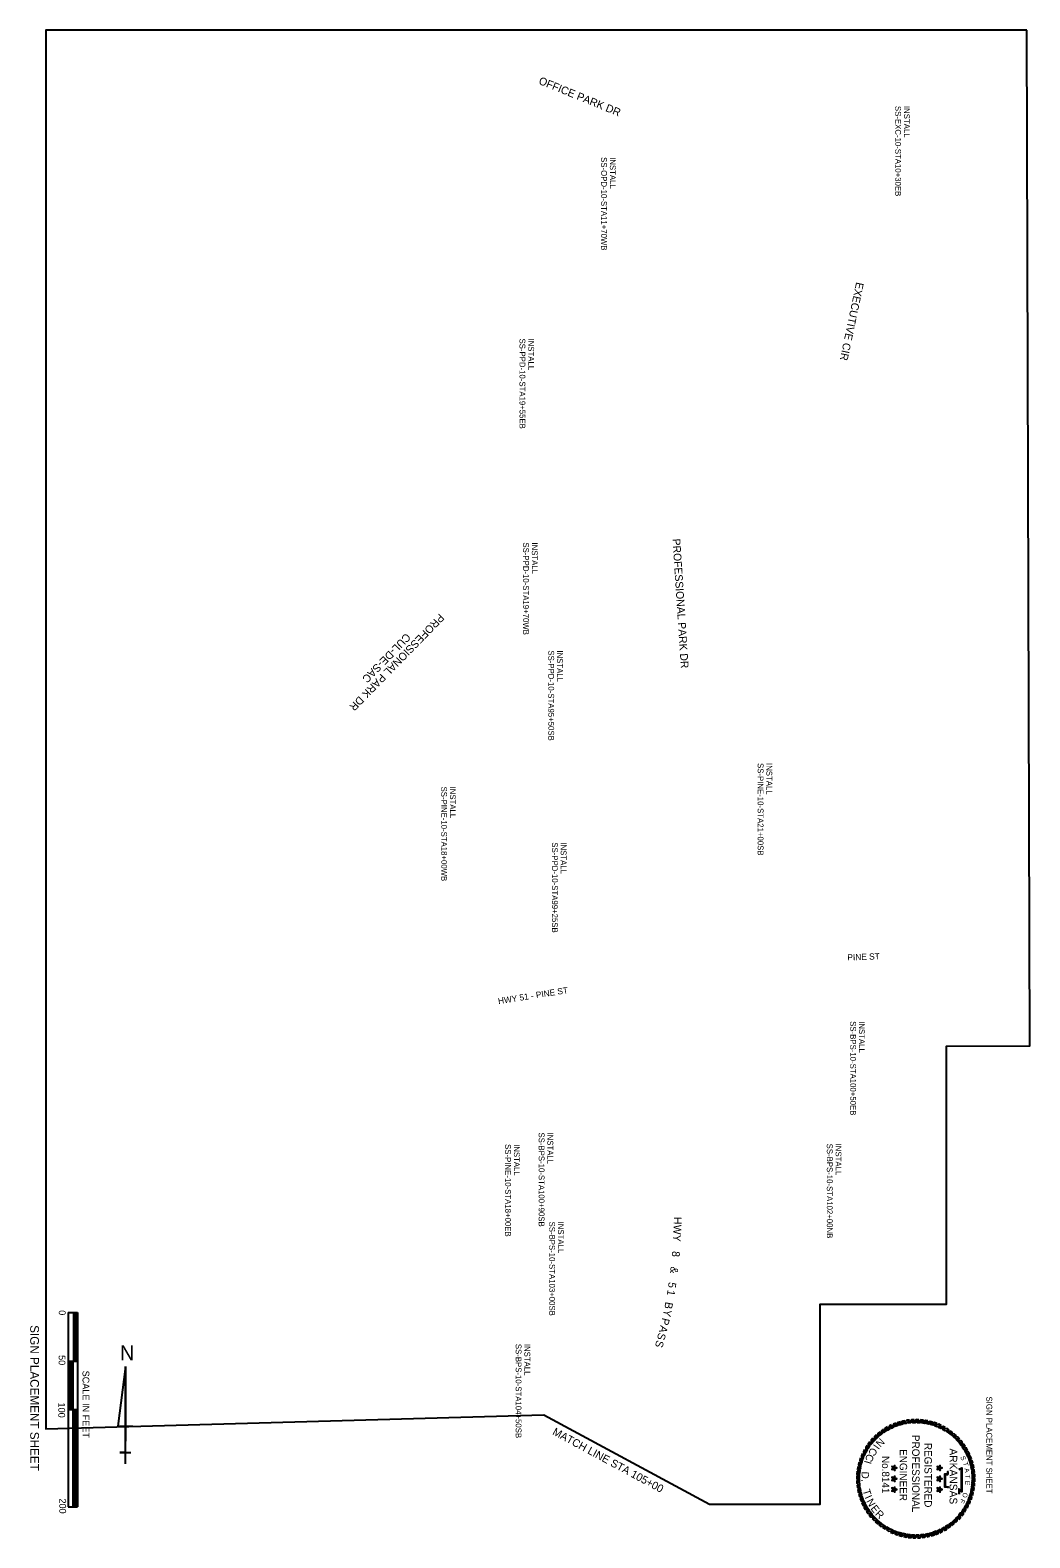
# Model space of a CAD drawing. Extents: x 981987 to 983016, y 1842087 to 1843638.
import ezdxf

# ---------------------------------------------------------------- set-up
doc = ezdxf.new("R2010")
doc.units = 0
for name, color, linetype in [('5', 7, 'Continuous'), ('63', 7, 'Continuous'), ('G-ANNO-SYMB', 7, 'Continuous'), ('G-ANNO-TEXT', 7, 'Continuous'), ('Level 10', 7, 'Continuous'), ('Plan Notes', 7, 'Continuous'), ('R_Annotation', 7, 'Continuous'), ('R_No Plot', 7, 'Continuous')]:
    doc.layers.add(name, color=color, linetype=linetype)

msp = doc.modelspace()

# ---------------------------------------------------------------- linework, layer by layer
at = {"layer": '5'}
msp.add_line((982515.7, 1842213.5), (982686.3, 1842121.4), dxfattribs=at)
at = {"layer": '63'}
for p, q in [((982085, 1842263.2), (982077.3, 1842201.7)), ((982085, 1842163.2), (982085, 1842263.2)), ((982085, 1842263.2), (982085, 1842186.3)), ((982077.3, 1842201.7), (982092.6, 1842201.7)), ((982085, 1842174.7), (982079.2, 1842174.7)), ((982079.2, 1842174.7), (982090.7, 1842174.7)), ((982085, 1842163.2), (982085, 1842186.3)), ((982085, 1842163.2), (982085, 1842174.7))]:
    msp.add_line(p, q, dxfattribs=at)
at = {"layer": 'G-ANNO-SYMB'}
for points in [[(982882.6, 1842206.4), (982880.1, 1842205.6), (982877.5, 1842201.8), (982880.1, 1842202.7)], [(982887.3, 1842207.4), (982884.7, 1842206.9), (982881.8, 1842203.2), (982884.5, 1842204)], [(982892, 1842208.1), (982889.4, 1842207.8), (982886.2, 1842204.4), (982889, 1842204.9)], [(982896.7, 1842208.4), (982894.1, 1842208.3), (982890.7, 1842205.2), (982893.5, 1842205.5)], [(982901.5, 1842208.4), (982898.9, 1842208.5), (982895.2, 1842205.6), (982898.1, 1842205.7)], [(982906.3, 1842208), (982903.7, 1842208.2), (982899.8, 1842205.7), (982902.6, 1842205.5)], [(982911, 1842207.2), (982908.4, 1842207.7), (982904.3, 1842205.4), (982907.1, 1842205)], [(982915.6, 1842206), (982913.1, 1842206.7), (982908.8, 1842204.8), (982911.6, 1842204.2)], [(982920.1, 1842204.5), (982917.7, 1842205.4), (982913.3, 1842203.8), (982916, 1842203)], [(982857.7, 1842192.8), (982855.8, 1842191), (982855.2, 1842186.3), (982857.2, 1842188.4)], [(982861.4, 1842195.8), (982859.3, 1842194.2), (982858.4, 1842189.6), (982860.5, 1842191.5)], [(982865.2, 1842198.6), (982863.1, 1842197.1), (982861.8, 1842192.6), (982864, 1842194.4)], [(982869.3, 1842201), (982867.1, 1842199.7), (982865.4, 1842195.4), (982867.8, 1842196.9)], [(982873.6, 1842203.2), (982871.3, 1842202), (982869.3, 1842197.8), (982871.8, 1842199.2)], [(982878, 1842204.9), (982875.6, 1842204), (982873.3, 1842199.9), (982875.9, 1842201.1)], [(982924.5, 1842202.6), (982922.1, 1842203.7), (982917.6, 1842202.4), (982920.3, 1842201.4)], [(982928.7, 1842200.4), (982926.5, 1842201.6), (982921.9, 1842200.8), (982924.4, 1842199.6)], [(982932.8, 1842197.9), (982930.6, 1842199.3), (982926, 1842198.8), (982928.4, 1842197.4)], [(982936.6, 1842195), (982934.6, 1842196.6), (982929.9, 1842196.4), (982932.2, 1842194.9)], [(982940.2, 1842191.9), (982938.3, 1842193.6), (982933.6, 1842193.8), (982935.8, 1842192.1)], [(982943.6, 1842188.5), (982941.8, 1842190.4), (982937.1, 1842190.9), (982939.2, 1842189)], [(982845.8, 1842177.9), (982844.5, 1842175.7), (982845.4, 1842171.1), (982846.6, 1842173.6)], [(982848.3, 1842182), (982846.9, 1842179.8), (982847.4, 1842175.2), (982848.8, 1842177.6)], [(982851.1, 1842185.8), (982849.5, 1842183.7), (982849.7, 1842179.1), (982851.3, 1842181.4)], [(982854.3, 1842189.4), (982852.5, 1842187.5), (982852.3, 1842182.8), (982854.1, 1842185)], [(982946.6, 1842184.8), (982945, 1842186.8), (982940.4, 1842187.8), (982942.3, 1842185.7)], [(982949.4, 1842180.9), (982947.9, 1842183.1), (982943.4, 1842184.4), (982945.2, 1842182.1)], [(982951.8, 1842176.8), (982950.5, 1842179.1), (982946.2, 1842180.7), (982947.7, 1842178.4)], [(982954, 1842172.5), (982952.8, 1842174.9), (982948.6, 1842176.9), (982950, 1842174.4)], [(982839, 1842160.2), (982838.5, 1842157.6), (982840.8, 1842153.5), (982841.1, 1842156.3)], [(982840.1, 1842164.8), (982839.5, 1842162.3), (982841.4, 1842158), (982842, 1842160.8)], [(982841.7, 1842169.3), (982840.8, 1842166.9), (982842.4, 1842162.5), (982843.2, 1842165.2)], [(982843.5, 1842173.7), (982842.5, 1842171.3), (982843.7, 1842166.8), (982844.7, 1842169.5)], [(982876.1, 1842158.8), (982875.8, 1842159.8), (982873.9, 1842160.4), (982875.1, 1842158.8)], [(982876.1, 1842158.8), (982875.1, 1842158.8), (982873.9, 1842157.2), (982875.8, 1842157.8)], [(982876.1, 1842158.8), (982877, 1842159.4), (982877, 1842161.4), (982875.8, 1842159.8)], [(982876.1, 1842158.8), (982875.8, 1842157.8), (982877, 1842156.1), (982877, 1842158.2)], [(982876.1, 1842158.8), (982877, 1842158.2), (982878.9, 1842158.8), (982877, 1842159.4)], [(982922.7, 1842158.8), (982922.4, 1842159.8), (982920.4, 1842160.4), (982921.6, 1842158.8)], [(982922.7, 1842158.8), (982921.6, 1842158.8), (982920.4, 1842157.2), (982922.4, 1842157.8)], [(982922.7, 1842158.8), (982923.5, 1842159.4), (982923.5, 1842161.4), (982922.4, 1842159.8)], [(982922.7, 1842158.8), (982922.4, 1842157.8), (982923.5, 1842156.1), (982923.5, 1842158.2)], [(982922.7, 1842158.8), (982923.5, 1842158.2), (982925.5, 1842158.8), (982923.5, 1842159.4)], [(982955.7, 1842168.1), (982954.8, 1842170.5), (982950.7, 1842172.8), (982951.9, 1842170.3)], [(982957.2, 1842163.6), (982956.4, 1842166.1), (982952.6, 1842168.7), (982953.5, 1842166)], [(982958.2, 1842158.9), (982957.7, 1842161.5), (982954, 1842164.4), (982954.8, 1842161.6)], [(982958.9, 1842154.2), (982958.6, 1842156.8), (982955.2, 1842159.9), (982955.7, 1842157.2)], [(982837.8, 1842150.7), (982837.7, 1842148.1), (982840.6, 1842144.4), (982840.5, 1842147.2)], [(982837.7, 1842145.9), (982837.8, 1842143.3), (982841, 1842139.9), (982840.7, 1842142.7)], [(982838.2, 1842155.5), (982837.9, 1842152.9), (982840.5, 1842149), (982840.6, 1842151.8)], [(982876.1, 1842147.7), (982875.8, 1842148.7), (982873.9, 1842149.3), (982875.1, 1842147.7)], [(982876.1, 1842147.7), (982875.1, 1842147.7), (982873.9, 1842146), (982875.8, 1842146.7)], [(982876.1, 1842147.7), (982877, 1842148.3), (982877, 1842150.3), (982875.8, 1842148.7)], [(982876.1, 1842147.7), (982875.8, 1842146.7), (982877, 1842145), (982877, 1842147.1)], [(982876.1, 1842147.7), (982877, 1842147.1), (982878.9, 1842147.7), (982877, 1842148.3)], [(982922.7, 1842147.7), (982922.4, 1842148.7), (982920.4, 1842149.3), (982921.6, 1842147.7)], [(982922.7, 1842147.7), (982921.6, 1842147.7), (982920.4, 1842146), (982922.4, 1842146.7)], [(982922.7, 1842147.7), (982923.5, 1842148.3), (982923.5, 1842150.3), (982922.4, 1842148.7)], [(982922.7, 1842147.7), (982922.4, 1842146.7), (982923.5, 1842145), (982923.5, 1842147.1)], [(982922.7, 1842147.7), (982923.5, 1842147.1), (982925.5, 1842147.7), (982923.5, 1842148.3)], [(982959.2, 1842149.4), (982959.1, 1842152), (982956, 1842155.5), (982956.3, 1842152.7)], [(982958.8, 1842139.9), (982959, 1842142.5), (982956.5, 1842146.4), (982956.3, 1842143.5)], [(982959.2, 1842144.6), (982959.3, 1842147.3), (982956.4, 1842150.9), (982956.5, 1842148.1)], [(982838, 1842141.2), (982838.4, 1842138.6), (982841.8, 1842135.4), (982841.2, 1842138.2)], [(982838.7, 1842136.5), (982839.3, 1842133.9), (982842.9, 1842131), (982842.2, 1842133.7)], [(982839.8, 1842131.8), (982840.5, 1842129.3), (982844.4, 1842126.7), (982843.4, 1842129.3)], [(982876.1, 1842136.6), (982875.8, 1842137.6), (982873.9, 1842138.2), (982875.1, 1842136.6)], [(982876.1, 1842136.6), (982875.1, 1842136.6), (982873.9, 1842134.9), (982875.8, 1842135.6)], [(982876.1, 1842136.6), (982877, 1842137.2), (982877, 1842139.2), (982875.8, 1842137.6)], [(982876.1, 1842136.6), (982875.8, 1842135.6), (982877, 1842133.9), (982877, 1842135.9)], [(982876.1, 1842136.6), (982877, 1842135.9), (982878.9, 1842136.6), (982877, 1842137.2)], [(982922.7, 1842136.6), (982922.4, 1842137.6), (982920.4, 1842138.2), (982921.6, 1842136.6)], [(982922.7, 1842136.6), (982921.6, 1842136.6), (982920.4, 1842134.9), (982922.4, 1842135.6)], [(982922.7, 1842136.6), (982923.5, 1842137.2), (982923.5, 1842139.2), (982922.4, 1842137.6)], [(982922.7, 1842136.6), (982922.4, 1842135.6), (982923.5, 1842133.9), (982923.5, 1842135.9)], [(982922.7, 1842136.6), (982923.5, 1842135.9), (982925.5, 1842136.6), (982923.5, 1842137.2)], [(982953.4, 1842121.6), (982954.5, 1842124), (982953.2, 1842128.5), (982952.2, 1842125.9)], [(982955.3, 1842126), (982956.2, 1842128.5), (982954.6, 1842132.9), (982953.8, 1842130.2)], [(982956.8, 1842130.6), (982957.5, 1842133.1), (982955.6, 1842137.3), (982955, 1842134.5)], [(982958, 1842135.2), (982958.5, 1842137.7), (982956.2, 1842141.8), (982955.8, 1842139)], [(982841.2, 1842127.2), (982842.2, 1842124.8), (982846.2, 1842122.5), (982845, 1842125.1)], [(982843, 1842122.8), (982844.1, 1842120.5), (982848.3, 1842118.5), (982847, 1842121)], [(982845.1, 1842118.5), (982846.4, 1842116.3), (982850.8, 1842114.6), (982849.2, 1842117)], [(982847.6, 1842114.4), (982849.1, 1842112.3), (982853.5, 1842111), (982851.8, 1842113.2)], [(982942.7, 1842105.9), (982944.4, 1842107.9), (982944.6, 1842112.5), (982942.9, 1842110.3)], [(982945.8, 1842109.5), (982947.4, 1842111.6), (982947.2, 1842116.3), (982945.7, 1842113.9)], [(982948.7, 1842113.4), (982950.1, 1842115.6), (982949.6, 1842120.2), (982948.2, 1842117.7)], [(982951.2, 1842117.4), (982952.5, 1842119.7), (982951.6, 1842124.3), (982950.4, 1842121.7)], [(982850.3, 1842110.6), (982852, 1842108.5), (982856.5, 1842107.6), (982854.6, 1842109.7)], [(982853.4, 1842106.9), (982855.2, 1842105), (982859.8, 1842104.4), (982857.8, 1842106.4)], [(982856.7, 1842103.5), (982858.7, 1842101.7), (982863.3, 1842101.5), (982861.1, 1842103.3)], [(982860.3, 1842100.3), (982862.4, 1842098.7), (982867.1, 1842098.9), (982864.7, 1842100.5)], [(982864.2, 1842097.5), (982866.4, 1842096.1), (982871, 1842096.6), (982868.5, 1842098)], [(982923.3, 1842092.2), (982925.7, 1842093.3), (982927.7, 1842097.5), (982925.2, 1842096.2)], [(982927.6, 1842094.3), (982929.9, 1842095.6), (982931.5, 1842100), (982929.2, 1842098.4)], [(982931.7, 1842096.8), (982933.9, 1842098.2), (982935.2, 1842102.7), (982932.9, 1842101)], [(982935.6, 1842099.5), (982937.6, 1842101.2), (982938.6, 1842105.7), (982936.5, 1842103.8)], [(982939.3, 1842102.6), (982941.2, 1842104.4), (982941.7, 1842109), (982939.8, 1842107)], [(982868.2, 1842095), (982870.5, 1842093.7), (982875.1, 1842094.6), (982872.5, 1842095.8)], [(982872.4, 1842092.7), (982874.8, 1842091.7), (982879.3, 1842092.9), (982876.7, 1842093.9)], [(982876.8, 1842090.9), (982879.3, 1842090), (982883.7, 1842091.6), (982881, 1842092.4)], [(982881.4, 1842089.3), (982883.9, 1842088.7), (982888.1, 1842090.6), (982885.4, 1842091.2)], [(982886, 1842088.2), (982888.6, 1842087.7), (982892.6, 1842090), (982889.8, 1842090.3)], [(982890.7, 1842087.4), (982893.3, 1842087.1), (982897.2, 1842089.7), (982894.4, 1842089.8)], [(982895.4, 1842087), (982898.1, 1842086.9), (982901.7, 1842089.8), (982898.9, 1842089.7)], [(982900.2, 1842086.9), (982902.8, 1842087), (982906.3, 1842090.2), (982903.5, 1842089.9)], [(982905, 1842087.2), (982907.6, 1842087.6), (982910.7, 1842091), (982908, 1842090.4)], [(982909.7, 1842087.9), (982912.3, 1842088.5), (982915.2, 1842092.1), (982912.4, 1842091.4)], [(982914.4, 1842089), (982916.9, 1842089.7), (982919.5, 1842093.6), (982916.8, 1842092.6)], [(982918.9, 1842090.4), (982921.4, 1842091.4), (982923.6, 1842095.4), (982921.1, 1842094.2)]]:
    msp.add_lwpolyline(points, close=True, dxfattribs=at)
for points in [[(982942.6, 1842157.4), (982945.7, 1842158.8), (982945.7, 1842134.3), (982943.1, 1842136.4), (982943.1, 1842134.7), (982943.1, 1842133.3), (982943, 1842131.9)], [(982932.3, 1842138.2), (982932, 1842138.6), (982931.5, 1842138.7), (982930.2, 1842138.9), (982928.5, 1842138.9), (982928.5, 1842152.6), (982930.8, 1842152.6), (982931.3, 1842152.6), (982931.5, 1842153.1), (982931.5, 1842155.1), (982932, 1842155.4)], [(982932.6, 1842138.4), (982932.2, 1842138.9), (982931.5, 1842139.1), (982930.2, 1842139.3), (982928.9, 1842139.3), (982928.9, 1842152.2), (982930.8, 1842152.2), (982931.6, 1842152.2), (982931.9, 1842153.1), (982931.9, 1842154.9), (982932.2, 1842155.1)], [(982942.8, 1842157.1), (982945.3, 1842158.2), (982945.3, 1842135.1), (982942.7, 1842137.2), (982942.7, 1842134.7), (982942.8, 1842133.3), (982942.6, 1842132)]]:
    msp.add_lwpolyline(points, dxfattribs=at)
at = {"layer": 'Level 10'}
for p, q in [((982026, 1842318.8), (982026, 1842118.8)), ((982026, 1842318.8), (982035.6, 1842318.8)), ((982031.6, 1842318.8), (982031.6, 1842268.8)), ((982032.4, 1842318.8), (982032.4, 1842268.8)), ((982033.2, 1842318.8), (982033.2, 1842268.8)), ((982034, 1842318.8), (982034, 1842268.8)), ((982034.8, 1842318.8), (982034.8, 1842268.8)), ((982035.6, 1842318.8), (982035.6, 1842158.8)), ((982035.6, 1842318.8), (982035.6, 1842278.8)), ((982026, 1842278.8), (982026, 1842238.8)), ((982026, 1842268.8), (982035.6, 1842268.8)), ((982026.8, 1842268.8), (982026.8, 1842218.8)), ((982027.6, 1842268.8), (982027.6, 1842218.8)), ((982028.4, 1842268.8), (982028.4, 1842218.8)), ((982029.2, 1842268.8), (982029.2, 1842218.8)), ((982030, 1842268.8), (982030, 1842218.8)), ((982030.8, 1842268.8), (982030.8, 1842218.8)), ((982035.6, 1842238.8), (982035.6, 1842118.8)), ((982026, 1842218.8), (982035.6, 1842218.8)), ((982030.8, 1842218.8), (982030.8, 1842158.8)), ((982030.8, 1842218.8), (982030.8, 1842118.8)), ((982031.6, 1842218.8), (982031.6, 1842118.8)), ((982032.4, 1842218.8), (982032.4, 1842118.8)), ((982033.2, 1842218.8), (982033.2, 1842118.8)), ((982034, 1842218.8), (982034, 1842118.8)), ((982034.8, 1842218.8), (982034.8, 1842118.8)), ((982026, 1842118.8), (982035.6, 1842118.8))]:
    msp.add_line(p, q, dxfattribs=at)
at = {"layer": 'R_No Plot'}
msp.add_lwpolyline([(983012.9, 1843638.2), (982003.2, 1843638.2), (982003.2, 1842199.2), (982515.7, 1842213.5), (982686.3, 1842121.4), (982800.1, 1842121.4), (982800.1, 1842327.4), (982929.9, 1842327.4), (982929.9, 1842592.9), (983015.9, 1842593.2)], close=True, dxfattribs=at)

# ---------------------------------------------------------------- texts
at = {"layer": '63'}
msp.add_text('N', height=15.4, dxfattribs=at).set_placement((982079.3, 1842269.6))
at = {"layer": 'G-ANNO-SYMB'}
for s, height, rotation, p in [('PROFESSIONAL', 7.642, 270, (982894.7, 1842192.8)), ('C', 7.64, 238.6873, (982853, 1842180.5)), ('I', 7.64, 234.2141, (982855.7, 1842183.9)), ('N', 7.64, 225.2676, (982861.8, 1842190.1)), ('ENGINEER', 7.64, 270, (982881.9, 1842178.2)), ('REGISTERED', 7.64, 270, (982907.4, 1842184.6)), ('ARKANSAS', 7.89, 270, (982933.2, 1842178.9)), ('I', 7.64, 254.3437, (982845.8, 1842167)), ('C', 7.64, 246.5155, (982848.9, 1842174)), ('No.8141', 7.61, 270, (982863.7, 1842171.1)), ('S', 4.84, 289.7726, (982944.2, 1842170.2)), ('T', 4.84, 286.9015, (982947, 1842164)), ('.', 7.64, 274.846, (982842.4, 1842147.3)), ('D', 7.64, 266.6451, (982842.9, 1842155.3)), ('A', 4.84, 278.6788, (982948.5, 1842158.2)), ('E', 4.84, 266.672, (982949.3, 1842145.7)), ('T', 4.84, 271.4789, (982949.5, 1842151.9)), ('T', 7.64, 286.7747, (982843.7, 1842135.7)), ('I', 7.64, 294.2301, (982845.7, 1842128.7)), ('N', 7.64, 298.7033, (982847.3, 1842124.6)), ('O', 4.84, 251.2218, (982947.7, 1842134)), ('E', 7.64, 307.6498, (982851.5, 1842117)), ('R', 7.64, 315.478, (982856.1, 1842110.9)), ('F', 4.84, 245.3628, (982945.1, 1842127.5))]:
    msp.add_text(s, height=height, rotation=rotation, dxfattribs=at).set_placement(p)
at = {"layer": 'G-ANNO-TEXT'}
for height, p in [(9, (981987, 1842305.7)), (6, (982971.1, 1842232.3))]:
    msp.add_text('SIGN PLACEMENT SHEET', height=height, rotation=270, dxfattribs=at).set_placement(p)
at = {"layer": 'Level 10'}
for s, height, p in [('0', 7, (982016.4, 1842321.1)), ('50', 7, (982016.2, 1842274.9)), ('SCALE IN FEET', 7.001, (982040.8, 1842258.9)), ('100', 7, (982015.9, 1842226.1)), ('200', 7, (982016.9, 1842127.4))]:
    msp.add_text(s, height=height, rotation=270.0003, dxfattribs=at).set_placement(p)
at = {"layer": 'Plan Notes'}
for s, height, rotation, p in [('OFFICE PARK DR', 8, 337.8527, (982509.6, 1843583.1)), ('EXECUTIVE CIR', 8, 258.0569, (982837.2, 1843379.3)), ('PROFESSIONAL PARK DR', 8, 273.7353, (982648, 1843114.7)), ('PROFESSIONAL PARK DR', 8, 225.7353, (982408.2, 1843038.3)), ('CUL-DE-SAC', 8, 225.7353, (982373.7, 1843018.3)), ('PINE ST', 6.4, 2.0981, (982828.2, 1842680.9)), ('HWY 51 - PINE ST', 6.4, 9.0981, (982469, 1842635.9)), ('W', 8, 267.8562, (982649.3, 1842409.2)), ('H', 8, 268.7249, (982649.5, 1842417.2)), ('Y', 8, 266.7417, (982648.9, 1842399)), ('8', 8, 264.9224, (982647.8, 1842382.2)), ('&', 8, 263.1851, (982646.3, 1842366.3)), ('5', 8, 261.4412, (982644.2, 1842350.4)), ('B', 8, 259.2116, (982640.9, 1842330.1)), ('1', 8, 260.5726, (982643.1, 1842342.5)), ('Y', 8, 258.3429, (982639.5, 1842322.3)), ('A', 8, 255.8125, (982635.7, 1842305.9)), ('P', 8, 256.6811, (982637.6, 1842313.7)), ('S', 8, 254.1165, (982631.8, 1842290.8)), ('S', 8, 254.9852, (982633.8, 1842298.5)), ('MATCH LINE STA 105+00', 8, 331.634, (982523.8, 1842193.6))]:
    msp.add_text(s, height=height, rotation=rotation, dxfattribs=at).set_placement(p)
at = {"layer": 'R_Annotation'}
for s, p in [('SS-EXC-10-STA10+30EB', (982877.3, 1843560.2)), ('INSTALL', (982886.3, 1843560.2)), ('SS-OPD-10-STA11+70WB', (982574.6, 1843507.5)), ('INSTALL', (982583.6, 1843507.5)), ('SS-PPD-10-STA19+55EB', (982490.6, 1843320.9)), ('INSTALL', (982499.6, 1843320.9)), ('SS-PPD-10-STA19+70WB', (982494.3, 1843111.1)), ('INSTALL', (982503.3, 1843111.1)), ('SS-PPD-10-STA95+50SB', (982520.2, 1843000)), ('INSTALL', (982529.2, 1843000)), ('SS-PINE-10-STA21+00SB', (982735.7, 1842884.1)), ('INSTALL', (982744.7, 1842884.1)), ('SS-PINE-10-STA18+00WB', (982410, 1842859.9)), ('INSTALL', (982419, 1842859.9)), ('SS-PPD-10-STA99+25SB', (982524, 1842802.5)), ('INSTALL', (982533, 1842802.5)), ('SS-BPS-10-STA100+50EB', (982831, 1842618.5)), ('INSTALL', (982840, 1842618.5)), ('SS-BPS-10-STA100+90SB', (982510.3, 1842504)), ('INSTALL', (982519.3, 1842504)), ('SS-PINE-10-STA18+00EB', (982475.8, 1842492)), ('INSTALL', (982484.8, 1842492)), ('SS-BPS-10-STA102+00NB', (982806.9, 1842492.5)), ('INSTALL', (982815.9, 1842492.5)), ('SS-BPS-10-STA103+00SB', (982521.2, 1842412.3)), ('INSTALL', (982530.2, 1842412.3)), ('SS-BPS-10-STA104+50SB', (982486.6, 1842286.5)), ('INSTALL', (982495.6, 1842286.5))]:
    msp.add_text(s, height=6, rotation=270, dxfattribs=at).set_placement(p)

doc.saveas('drawing.dxf')
